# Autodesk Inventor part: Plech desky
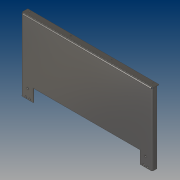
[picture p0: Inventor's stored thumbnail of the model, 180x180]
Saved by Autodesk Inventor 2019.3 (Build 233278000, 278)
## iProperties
Created: 2019-02
Part Number: Plech desky
Material: Nerezová ocel
Document SubType Name: Plech
Designer: B-hon
Density: 8 g/cm^3
Sheet Metal Rule: Výchozí_mm
Appearance: Ocel – leštěná
Author: B-hon
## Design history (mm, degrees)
node "Plocha1"
  sketch "Náčrt1"
    geometry: L1 (65, 0)-(635, 0) reference; L2 (700, 340)-(0, 340); L3 (65, 0)-(65, -45); L4 (65, -45)-(0, -45) reference; L5 (700, -45)-(635, -45) reference; L6 (635, -45)-(635, 0); L7 (0, 340)-(0, -45); L8 (700, 340)-(700, -45); 2 further points
    constraints: 16 end point, 4 horizontal, 2 vertical, 1 midpoint, 1 parallel, 1 other
    dimensions: "d1" = 340 distance of L2.end point (0, 0)
node "Obruba1"
sketch "Náčrt6"
  geometry: L1 (65, 0)-(65, -45) reference; L2 (65, -45)-(0, -45) reference; 4 further points
  constraints: 1 horizontal alignment
  dimensions: "d71" = 21 distance of point (46, -38) point (25, -38); "d72" = 19 distance from line of L1 point (46, -38); "d73" = 7 distance from line of L2 point (46, -38); "d74" = 10.5 horizontal distance of point (46, -38) point (35.5, 7); "d75" = 52 distance from line of L2 point (35.5, 7)
hole "Díra4" sketch "Náčrt6" at (25, -38), (46, -38), (35.5, 7) diameter "d76" = 5.5; stored, may be unused: countersink angle "d80" = 90 deg, drill point angle "d82" = 118 deg; dims "d77" = 6, "d78" = 10.4, "d79" = 2, "d81" = 3 (= Tloušťka)
pattern_linear "Obdélníkové pole5" dims "d85" = 629
sketch "Náčrt9"
  geometry: L1 (100, 5)-(145, 5); L2 (145, 5)-(145, -23.841); L3 (145, -23.841)-(100, -23.841); L4 (100, -23.841)-(100, 5); L5 (555, 5)-(600, 5); L6 (600, 5)-(600, -39.467); L7 (600, -39.467)-(555, -39.467); L8 (555, -39.467)-(555, 5); L9 (0, -45)-(0, 334) reference; L10 (700, 334)-(700, -45) reference; L11 (635, 0)-(65, 0) reference; 1 further point
  constraints: 16 end point, 4 parallel, 2 horizontal, 2 perpendicular
  dimensions: "d98" = 100 distance between parallel lines of L4 L9; "d99" = 100 distance between parallel lines of L6 L10; "d100" = 5 distance between parallel lines of L11 L5; "d101" = 5 distance between parallel lines of L11 L1; "d102" = 45 distance of L6.end L7.end; "d103" = 45 distance of L2.end L3.end
extrude "Vysunutí1" cut sketch "Náčrt9" distance "d104" = 10; taper "d105" = 0 deg
node "Obruba2"
node "Obruba3"
sketch "Náčrt13"
  geometry: L1 (0, 0)-(700, 0) reference; L2 (0, -29)-(0, 0) reference; 2 further points
  dimensions: "d137" = 10 distance from line of L1 point (20, -10); "d138" = 20 distance from line of point (20, -10) L2
hole "Díra7" sketch "Náčrt13" at (20, -10) diameter "d139" = 5.5; stored, may be unused: countersink angle "d143" = 90 deg, drill point angle "d145" = 0 deg; dims "d140" = 6, "d141" = 9.5, "d142" = 2, "d144" = 3 (= Tloušťka)
pattern_linear "Obdélníkové pole7" dims "d148" = 220
sketch "Náčrt14"
  geometry: L1 (6, 334)-(6, -45) reference; L2 (65, -45)-(6, -45) reference; L3 (65, 0)-(65, -45) reference; L4 (100, 0)-(65, 0) reference; L5 (100, 0)-(100, 5) reference; L6 (100, 5)-(145, 5) reference; L7 (145, 5)-(145, 0) reference; L8 (555, 0)-(145, 0) reference; L9 (555, 0)-(555, 5) reference; L10 (555, 5)-(600, 5) reference; L11 (600, 5)-(600, 0) reference; L12 (635, 0)-(600, 0) reference; L13 (635, -45)-(635, 0) reference; L14 (694, -45)-(635, -45) reference; L15 (694, -45)-(694, 334) reference; L16 (694, 334)-(6, 334) reference; L17 (65, 0)-(635, 0); L18 (635, 0)-(635, 22); L19 (635, 22)-(65, 22); L20 (65, 22)-(65, 0); C1 r 5.2 at (35.5, 7) reference; C2 r 5.2 at (25, -38) reference; C3 r 5.2 at (46, -38) reference; C4 r 5.2 at (654, -38) reference; C5 r 5.2 at (664.5, 7) reference; C6 r 5.2 at (675, -38) reference; 1 further point
  constraints: 8 end point, 2 parallel, 1 horizontal, 1 perpendicular
  dimensions: "d149" = 15 distance from line of L19 C1.centre
extrude "Vysunutí2" cut sketch "Náčrt14" distance "d150" = 10; taper "d151" = 0 deg
node "Těleso1"
feature "Deska1" dims "d8" = 3 (= Tloušťka)
sketch "Náčrt2"
  geometry: L1 through (350, 0) direction (-1, 0); L2 through (0, -17.5) direction (0, -1); L3 (0, -35)-(700, -35); L4 (700, -35)-(700, 0)
  constraints: 6 end point, 1 horizontal, 1 perpendicular, 1 vertical
feature "Deska2" dims "d8" = 3 (= Tloušťka), "d9" = 3 (= ŠířkaVýštipu), "d10" = 1.5 (= HloubkaVýštipu), "d11" = 6 (= MinimálníZbytek), "d12" = 3 (= PřechodovýPoloměr), "d13" = 35, "d14" = 90 deg, "d15" = 3 (= PoloměrOhybu), "d16" = 12 (= VelikostRohovéhoVýštipu), "d17" = 3 (= VelikostMezery), "d18" = 3 (= VelikostJacobihoPoloměru), "MezeraVystřižení" = 0.01
feature "Ohyb1" dims "d8" = 3 (= Tloušťka), "d9" = 3 (= ŠířkaVýštipu), "d10" = 1.5 (= HloubkaVýštipu), "d11" = 6 (= MinimálníZbytek), "d12" = 3 (= PřechodovýPoloměr), "d13" = 35, "d14" = 90 deg, "d15" = 3 (= PoloměrOhybu), "MezeraVystřižení" = 0.01
feature "Roh1" dims "d13" = 35, "d14" = 90 deg, "d16" = 12 (= VelikostRohovéhoVýštipu), "d17" = 3 (= VelikostMezery), "d18" = 3 (= VelikostJacobihoPoloměru)
sketch "Náčrt10"
  geometry: L1 through (189.5, 0) direction (-1, 0); L2 through (0, -12.5) direction (0, -1); L3 (0, -25)-(379, -25); L4 (379, -25)-(379, 0)
  constraints: 6 end point, 1 horizontal, 1 perpendicular, 1 vertical
feature "Deska3" dims "d8" = 3 (= Tloušťka), "d106" = 3 (= ŠířkaVýštipu), "d107" = 1.5 (= HloubkaVýštipu), "d108" = 6 (= MinimálníZbytek), "d109" = 3 (= PřechodovýPoloměr), "d110" = 25, "d111" = 90 deg, "d112" = 3 (= PoloměrOhybu), "d113" = 12 (= VelikostRohovéhoVýštipu), "d114" = 3 (= VelikostMezery), "d115" = 3 (= VelikostJacobihoPoloměru), "MezeraVystřižení" = 0.01
feature "Ohyb2" dims "d8" = 3 (= Tloušťka), "d106" = 3 (= ŠířkaVýštipu), "d107" = 1.5 (= HloubkaVýštipu), "d108" = 6 (= MinimálníZbytek), "d109" = 3 (= PřechodovýPoloměr), "d110" = 25, "d111" = 90 deg, "d112" = 3 (= PoloměrOhybu), "MezeraVystřižení" = 0.01
feature "Roh2" dims "d110" = 25, "d111" = 90 deg, "d113" = 12 (= VelikostRohovéhoVýštipu), "d114" = 3 (= VelikostMezery), "d115" = 3 (= VelikostJacobihoPoloměru)
sketch "Náčrt11"
  geometry: L1 through (189.5, 0) direction (-1, -3.48e-35); L2 through (0, -12.5) direction (-8.16e-33, -1); L3 (0, -25)-(379, -25); L4 (379, -25)-(379, 0)
  constraints: 6 end point, 1 horizontal, 1 perpendicular, 1 vertical
feature "Deska4" dims "d8" = 3 (= Tloušťka), "d116" = 3 (= ŠířkaVýštipu), "d117" = 1.5 (= HloubkaVýštipu), "d118" = 6 (= MinimálníZbytek), "d119" = 3 (= PřechodovýPoloměr), "d120" = 25, "d121" = 90 deg, "d122" = 3 (= PoloměrOhybu), "d123" = 12 (= VelikostRohovéhoVýštipu), "d124" = 3 (= VelikostMezery), "d125" = 3 (= VelikostJacobihoPoloměru), "MezeraVystřižení" = 0.01
feature "Ohyb3" dims "d8" = 3 (= Tloušťka), "d116" = 3 (= ŠířkaVýštipu), "d117" = 1.5 (= HloubkaVýštipu), "d118" = 6 (= MinimálníZbytek), "d119" = 3 (= PřechodovýPoloměr), "d120" = 25, "d121" = 90 deg, "d122" = 3 (= PoloměrOhybu), "MezeraVystřižení" = 0.01
feature "Roh3" dims "d120" = 25, "d121" = 90 deg, "d123" = 12 (= VelikostRohovéhoVýštipu), "d124" = 3 (= VelikostMezery), "d125" = 3 (= VelikostJacobihoPoloměru)
node "Promítnutá smyčka1"
other parameters: "Tloušťka" = 3 (derived), "KSoučinitel" = 4.4, "PoloměrOhybu" = 3 (= Tloušťka), "ŠířkaVýštipu" = 3 (= Tloušťka), "HloubkaVýštipu" = 1.5 (= 0.5 x Tloušťka), "VelikostRohovéhoVýštipu" = 12 (= 4 x Tloušťka), "MinimálníZbytek" = 6 (= 2 x Tloušťka), "PřechodovýPoloměr" = 3 (= PoloměrOhybu), "VelikostJacobihoPoloměru" = 3 (= PoloměrOhybu), "VelikostMezery" = 3 (= Tloušťka)
